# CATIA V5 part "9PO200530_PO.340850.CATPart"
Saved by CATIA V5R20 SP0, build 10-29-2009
Part number: 9PO200530_PO.340850
Revision: ANY
Definition: UNKNOWN
Nomenclature: 9PO200530_PO.340850
Source: Unknown
Bounding box of the stored display mesh (mm): x -5 to 5, y 0 to 19.5, z -5 to 5
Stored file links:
  C:\Users\Utente\Desktop\IO LAVORO\3D X SITO CF\CUMSA\3D files PO\PO 200530\9PO200530_PO.340850.CATPart
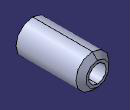
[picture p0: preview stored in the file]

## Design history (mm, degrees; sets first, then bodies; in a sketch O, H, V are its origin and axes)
Body1 "Chaflán2" (main body)
  Solid1: solid without history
